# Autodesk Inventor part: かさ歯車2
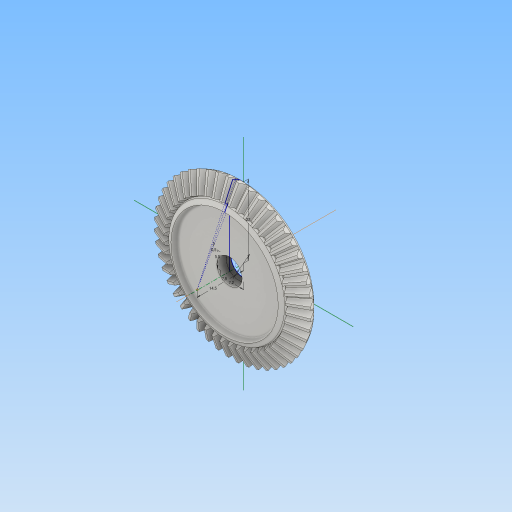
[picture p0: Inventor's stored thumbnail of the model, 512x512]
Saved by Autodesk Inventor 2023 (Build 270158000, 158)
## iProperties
CustomPartVersion: 1
Created: 2024-01
Part Number: かさ歯車2
Material: Steel, Mild
Document SubType Name: Modeling
Designer: kumagai
Categories: <?xml version="1.0" encoding="UTF-16"?> <MemberInstance><Categories><FamilyTemplate><FamilyTemplateParameter ValueType="xs:double" Id="1" ObjectReferenceKey="da
Mass: 60.9118 g
Surface Area: 34.3074 cm^2
Volume: 7.7496 cm^3
Density: 7.86 g/cm^3
Appearance: Steel
Author: kumagai
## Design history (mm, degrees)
node "上側の点"
node "メッシュ平面2"
sketch "歯のボディ スケッチ"
  geometry: L1 (0, 0)-(23.463, -13.073); L2 (23.463, -13.073)-(24.447, -11.106); L3 (24.447, -11.106)-(0, 0); L4 (24, -12)-(0, 0); L5 (18.217, -10.15)-(18.981, -8.622); L6 (23.463, -13.073)-(18.217, -10.15); L7 (24.447, -11.106)-(18.981, -8.622); L8 (0, -15.688)-(0, 2.615) reference; L9 (0, -12)-(24.447, -12); L10 (18.544, -9.496)-(16.755, -8.601); L11 (16.755, -8.601)-(15.861, -10.39); L12 (15.861, -10.39)-(17.65, -11.284); L13 (17.65, -11.284)-(18.544, -9.496); 2 further points
  constraints: 24 end point, 4 point on line, 3 collinear, 3 parallel, 3 perpendicular, 1 horizontal alignment, 1 vertical alignment
  dimensions: "d0" = 48 diameter of L4.start L8 (= da_de); "d1" = 46.92669 diameter of L1.end L8 (= da_dfe); "d2" = 48.89443 diameter of L2.end L8 (= da_dae); "d3" = 6 distance between parallel lines of L2 L5 (= da_b); "d4" = 11.10557 vertical distance of L2.end L1.start (= da_ve); "d94" = 0.2 distance between parallel lines of L4 L10; "d95" = 0 distance between parallel lines of L5 L13; "d96" = 2 distance between parallel lines of L13 L11; "d97" = 2 distance between parallel lines of L12 L10
revolve "歯のボディ" stored, may be unused: angle "d5" = 90 deg
node "始点"
node "歯の平面"
sketch "開始スケッチ"
  geometry: L1 (0, -64.732)-(0, 12.732) reference; L2 (-0.325, -1.464)-(0.325, -1.464); A1 r 18.703 centre (-18.347, -6.463) between (-0.325, -1.464) and (-1.49, 1.64); A2 r 18.703 centre (18.347, -6.463) between (1.49, 1.64) and (0.325, -1.464); A3 r 55.326 centre (0, -53.666) between (1.49, 1.64) and (-1.49, 1.64); 1 further point
  constraints: 6 point on circle, 3 centre point, 3 symmetric about line, 2 end point, 1 coincident, 1 perpendicular, 1 other
  dimensions: "d7" = 18.70268 radius of A1 (= fd_rr); "d8" = 18.34686 horizontal distance of point (0, -53.666) A1.centre (= fd_x); "d9" = 47.20293 vertical distance of point (0, -53.666) A1.centre (= fd_y); "d57" = 55.32563 radius of A3 (= 0.5 x fd_dva + 0.3 x da_he); "d58" = 52.20163 distance from line of A3.centre L2 (= 0.5 x fd_dva - 1.12 x da_he)
node "終了側の点"
  node "終了平面"
sketch "終了側スケッチ"
  geometry: L1 (0, -49.992)-(0, 9.833) reference; L2 (-0.251, -1.131)-(0.251, -1.131); A1 r 14.444 centre (-14.169, -4.991) between (-0.251, -1.131) and (-1.151, 1.266); A2 r 14.444 centre (14.169, -4.991) between (1.151, 1.266) and (0.251, -1.131); A3 r 42.728 centre (0, -41.446) between (1.151, 1.266) and (-1.151, 1.266); 1 further point
  constraints: 6 point on circle, 3 centre point, 3 symmetric about line, 2 end point, 1 coincident, 1 other
  dimensions: "d12" = 14.44396 radius of A1 (computed from fd_rr, fd_ratio); "d15" = 14.16917 horizontal distance of A1.centre point (0, -41.446) (computed from fd_x, fd_ratio); "d16" = 36.45453 vertical distance of A1.centre point (0, -41.446) (computed from fd_y, fd_ratio); "d59" = 42.72764 radius of A3 (computed from d57, fd_ratio); "d60" = 40.31499 distance from line of A3.centre L2 (computed from d58, fd_ratio)
feature "Loft" sketch "終了側スケッチ" dims "d17" = 0, "d18" = 90 deg, "d19" = 0, "d20" = 90 deg, "d89" = 0, "da_teethtype" = 0 [user parameter]
sketch "3D スケッチ(右)"
  node "Helical Curve Right" dims "d65" = 164.5695 (computed from da_dm, da_delta, da_beta), "d66" = 31.5, "d67" = 48 (= da_de), "d68" = -11.07149 (= -da_delta), "d69" = 2.73248 (computed from fd_loft, da_delta)
node "終了平面(右)"
sketch "終了側スケッチ(右)"
  geometry: L1 (0, -51.83)-(0, 11.671) reference; L2 (-0.251, -1.131)-(0.251, -1.131); A1 r 14.444 centre (-14.169, -4.991) between (-0.251, -1.131) and (-1.151, 1.266); A2 r 14.444 centre (14.169, -4.991) between (1.151, 1.266) and (0.251, -1.131); A3 r 42.728 centre (0, -41.446) between (1.151, 1.266) and (-1.151, 1.266); 1 further point
  constraints: 6 point on circle, 3 centre point, 3 symmetric about line, 2 end point, 1 coincident, 1 perpendicular, 1 other
  dimensions: "d70" = 14.16917 horizontal distance of A3.centre A1.centre (computed from fd_x, fd_ratio); "d71" = 36.45453 vertical distance of point (0, -41.446) A1.centre (computed from fd_y, fd_ratio); "d72" = 14.44396 radius of A1 (computed from fd_rr, fd_ratio); "d73" = 40.31499 distance from line of point (0, -41.446) L2 (computed from d58, fd_ratio); "d74" = 42.72764 radius of A3 (computed from d57, fd_ratio)
feature "ロフト(右)" sketch "終了側スケッチ(右)" dims "d75" = 0, "d77" = 0, "d79" = 0, "d80" = 90 deg, "d85" = 20, "d92" = 90 deg, "d93" = 90 deg, "da_teethtype" = 0 [user parameter]
sketch "3D スケッチ(左)"
  node "Helical Curve Left" dims "d26" = 164.5695 (computed from da_dm, da_delta, da_beta), "d27" = 2.73248 (computed from fd_loft, da_delta), "d28" = 48 (= da_de), "d29" = -11.07149 (= -da_delta)
node "終了平面(左)"
sketch "終了側スケッチ(左)" dims "d56" = 8.50902 (derived)
  geometry: L1 (0, -52.487)-(0, 12.379) reference; L2 (-0.251, -1.105)-(0.251, -1.105); A1 r 14.444 centre (-14.169, -4.966) between (-0.251, -1.105) and (-1.151, 1.292); A2 r 14.444 centre (14.169, -4.966) between (1.151, 1.292) and (0.251, -1.105); A3 r 42.728 centre (0, -41.42) between (1.151, 1.292) and (-1.151, 1.292); 2 further points; 1 other entity
  constraints: 6 point on circle, 3 centre point, 3 symmetric about line, 2 end point, 1 coincident, 2 other
  dimensions: "d30" = 14.44396 radius of A1 (computed from fd_rr, fd_ratio); "d31" = 14.16917 horizontal distance of point (0, -41.42) A1.centre (computed from fd_x, fd_ratio); "d32" = 36.45453 vertical distance of A1.centre point (0, -41.42) (computed from fd_y, fd_ratio); "d61" = 42.72764 radius of A3 (computed from d57, fd_ratio); "d62" = 40.31499 distance from line of point (0, -41.42) L2 (computed from d58, fd_ratio)
feature "ロフト(左)" sketch "終了側スケッチ(左)" dims "d35" = 0, "d37" = 0, "d39" = 0, "d40" = 90 deg, "d84" = 10, "d90" = 90 deg, "d91" = 90 deg, "da_teethtype" = 0 [user parameter]
sketch "ボディ スケッチ"
  geometry: L1 (0, -13.658)-(0, -9.565) reference; L2 (23.463, -13.073)-(18.217, -10.15) reference; L3 (18.217, -10.15)-(0, -10.15); L4 (23.463, -13.073)-(0, -13.073); L5 (23.463, -13.073)-(22, -14.5); L6 (22, -14.5)-(0, -14.5); L7 (0, -14.5)-(0, -13.073); 1 further point
  constraints: 10 end point, 3 point on line, 2 perpendicular, 1 horizontal
  dimensions: "d103" = 14.5 distance from line of point (0, 0) L6; "d125" = 22 distance from line of L7 L5.end
revolve "固定ボディ" stored, may be unused: angle "d46" = 90 deg
sketch "Sketch6"
  geometry: L1 (24, -12)-(0, 0) reference; L2 (0, -14.4)-(0, 2.4) reference
feature "ピッチ円直径" sketch "Sketch6" dims angle "d47" = 90 deg
revolve "回転3" stored, may be unused: angle "d98" = 360 deg
chamfer "面取り1" distance "d99" = 0.5; stored, may be unused: second distance "d100" = 0.4, angle "d101" = 45 deg
revolve "回転4" stored, may be unused: angle "d105" = 90 deg
sketch "スケッチ8"
  geometry: L1 (-7.2, -0.5)-(-7.2, -5.5); L2 (-7.2, -5.5)-(7.2, -5.5); L3 (7.2, -5.5)-(7.2, -0.5); L4 (-34.229, 0)-(34.229, 0) reference; L5 (0, -34.229)-(0, 34.229) reference; L6 (7.2, -0.5)-(3.918, -0.5); L7 (-3.918, -0.5)-(-7.2, -0.5); A1 r 3.95 centre (0, 0) between (-3.918, -0.5) and (3.918, -0.5); 4 further points
  constraints: 10 end point, 2 point on circle, 1 centre point, 1 coincident, 1 collinear, 1 other
  dimensions: "d106" = 7.9 diameter of A1; "d110" = 7.2 distance between parallel lines of L3 L5; "d111" = 5.5 distance between parallel lines of L4 L2; "d112" = 0.5 distance between parallel lines of L4 L6
extrude "押し出し1" cut sketch "スケッチ8" extent not by distance; stored distance "d113" = 0; taper "d114" = 0 deg
body "Solid1"
pattern_circular "Circular Pattern" dims angle "d22" = 360 deg, "d88" = 0, "da_teethtype" = 0 [user parameter]
pattern_circular "放射状パターン(右)" dims angle "d82" = 360 deg, "da_teethtype" = 0 [user parameter]
pattern_circular "放射状パターン(左)" dims angle "d42" = 360 deg, "da_teethtype" = 0 [user parameter]
body "Srf1"
node "ソリッド2"
node "ソリッド3"
other parameters: "da_b" = 6 [user parameter; used in 2 equation terms], "da_de" = 48 [user parameter; used in 4 equation terms], "da_dae" = 48.89443 [user parameter; used in 2 equation terms], "da_dfe" = 46.92669 [user parameter; used in 1 equation term], "da_le" = 26.83282 [user parameter; used in 1 equation term], "da_omega" = 90 deg [user parameter; used in 1 equation term], "da_beta" = 0 [user parameter; used in 2 equation terms], "da_delta" = 11.07149 [user parameter; used in 8 equation terms], "da_alpha" = 20 deg [user parameter; used in 2 equation terms], "da_he" = 2.2 [user parameter; used in 4 equation terms], "da_ve" = 11.10557 [user parameter; used in 1 equation term], "fd_dv" = 107.33126 (computed from da_de, da_delta) [user parameter; used in 1 equation term], "fd_dva" = 109.33126 (computed from da_dae, da_delta) [user parameter; used in 3 equation terms], "fd_dvb" = 100.8584 (computed from fd_dv, da_alpha) [user parameter; used in 2 equation terms], "da_zv" = 1073.31263 [user parameter; used in 1 equation term], "fd_loft" = 6.11 (= da_b + 0.05 x da_he) [user parameter; used in 4 equation terms], "fd_ratio" = 7.72294 (computed from da_le, fd_loft) [user parameter; used in 15 equation terms], "fd_rr" = 18.70268 (computed from fd_dd, fd_dvb) [user parameter; used in 6 equation terms], "fd_angle" = 0.14798 (computed from da_zv) [user parameter; used in 4 equation terms], "fd_x1" = 0.7941 (computed from da_dvw, fd_angle) [user parameter; used in 1 equation term], "fd_y1" = 53.65976 (computed from da_dvw, fd_angle) [user parameter; used in 1 equation term], "fd_x2" = 17.55277 (computed from fd_rr, fd_angle2, fd_angle) [user parameter; used in 1 equation term], "fd_y2" = 6.45682 (computed from fd_rr, fd_angle2, fd_angle) [user parameter; used in 1 equation term], "fd_x" = 18.34686 (= fd_x1 + fd_x2) [user parameter; used in 4 equation terms], "fd_y" = 47.20293 (= fd_y1 - fd_y2) [user parameter; used in 4 equation terms], "fd_angle2" = 3.37692 (computed from fd_dvb, fd_dd, da_alpha) [user parameter; used in 2 equation terms], "fd_dd" = 107.57126 (= fd_dva - 0.8 x da_he) [user parameter; used in 2 equation terms], "da_dvw" = 107.33126 [user parameter; used in 2 equation terms], "d11" = 6.11 (= fd_loft), "da_dm" = 42.63344 [user parameter; used in 2 equation terms], "da_x" = 0 [user parameter], "da_m" = 1 [user parameter], "d48" = 0, "d49" = 0, "d50" = 90 deg (= da_omega), "d51" = 0.6545 (computed from da_z), "d52" = 0, "d53" = 0, "d54" = 0
